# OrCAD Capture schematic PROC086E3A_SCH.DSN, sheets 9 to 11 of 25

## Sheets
9 10. CODEC-A STEREO_LINE_OUT: size C; title: CODEC-A STEREO LINE OUT
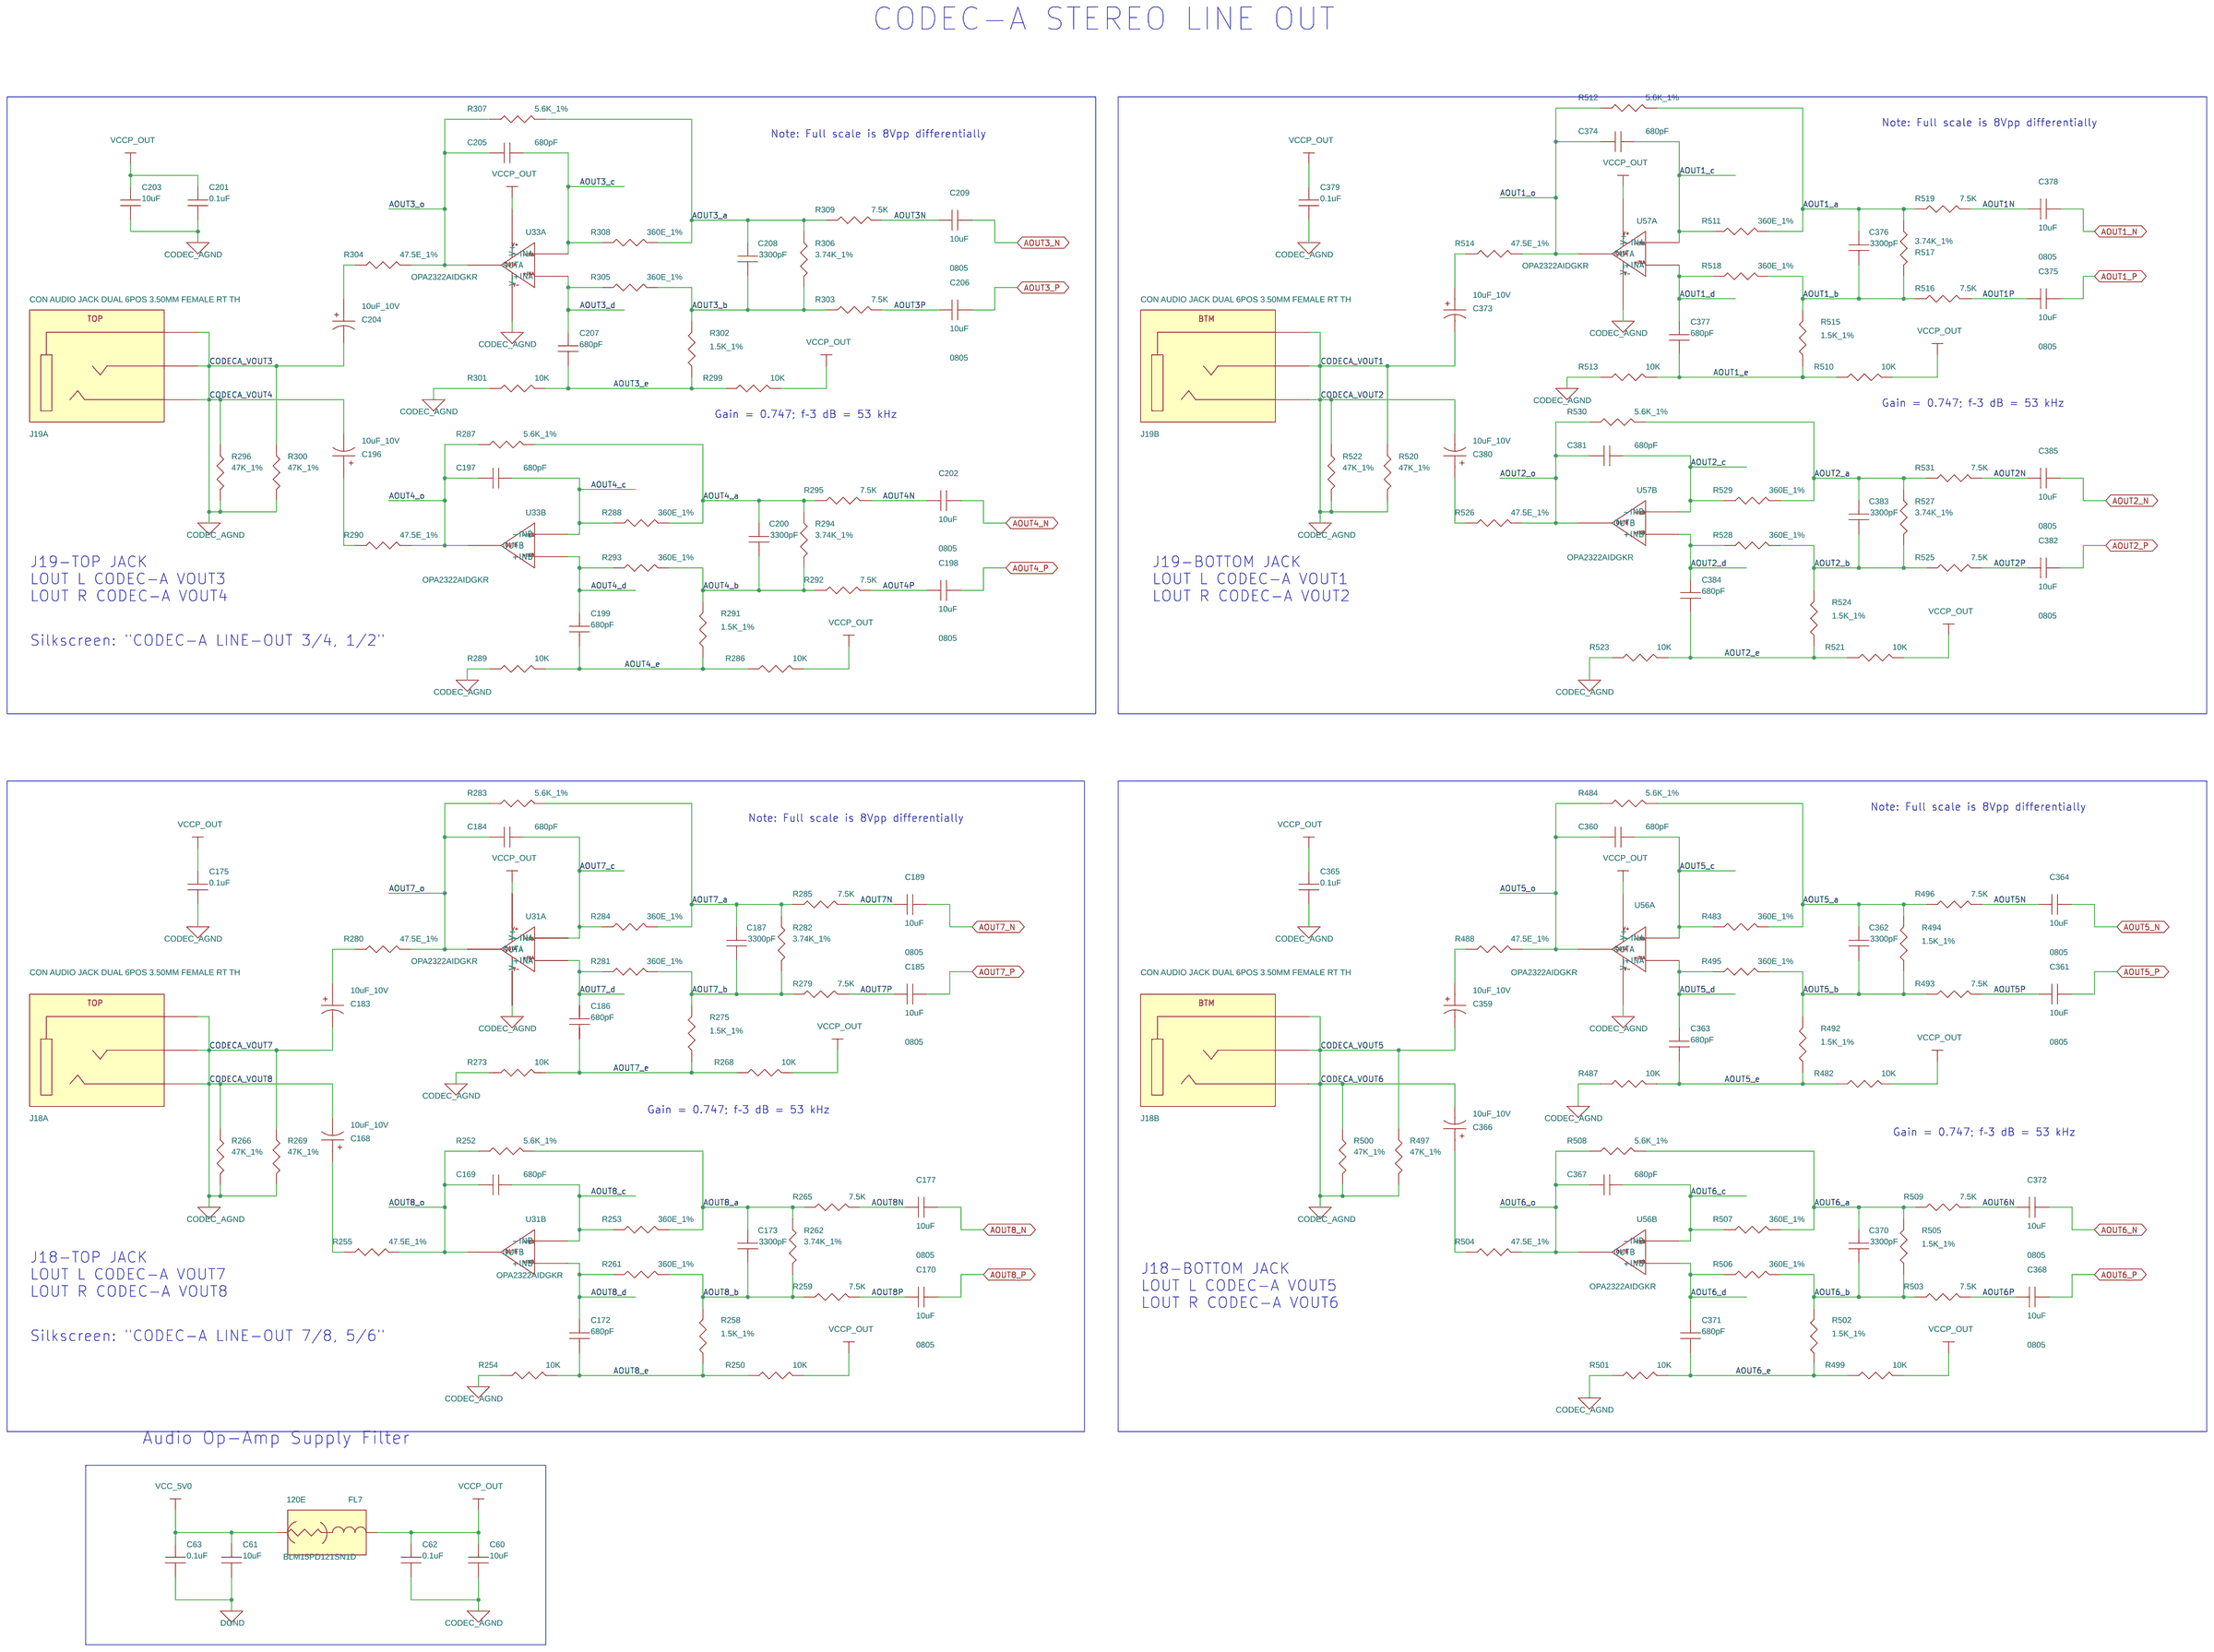
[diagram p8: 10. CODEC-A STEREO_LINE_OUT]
10 12. CODEC-B STEREO_LINE_IN: size C; title: CODEC-B STEREO LINE IN
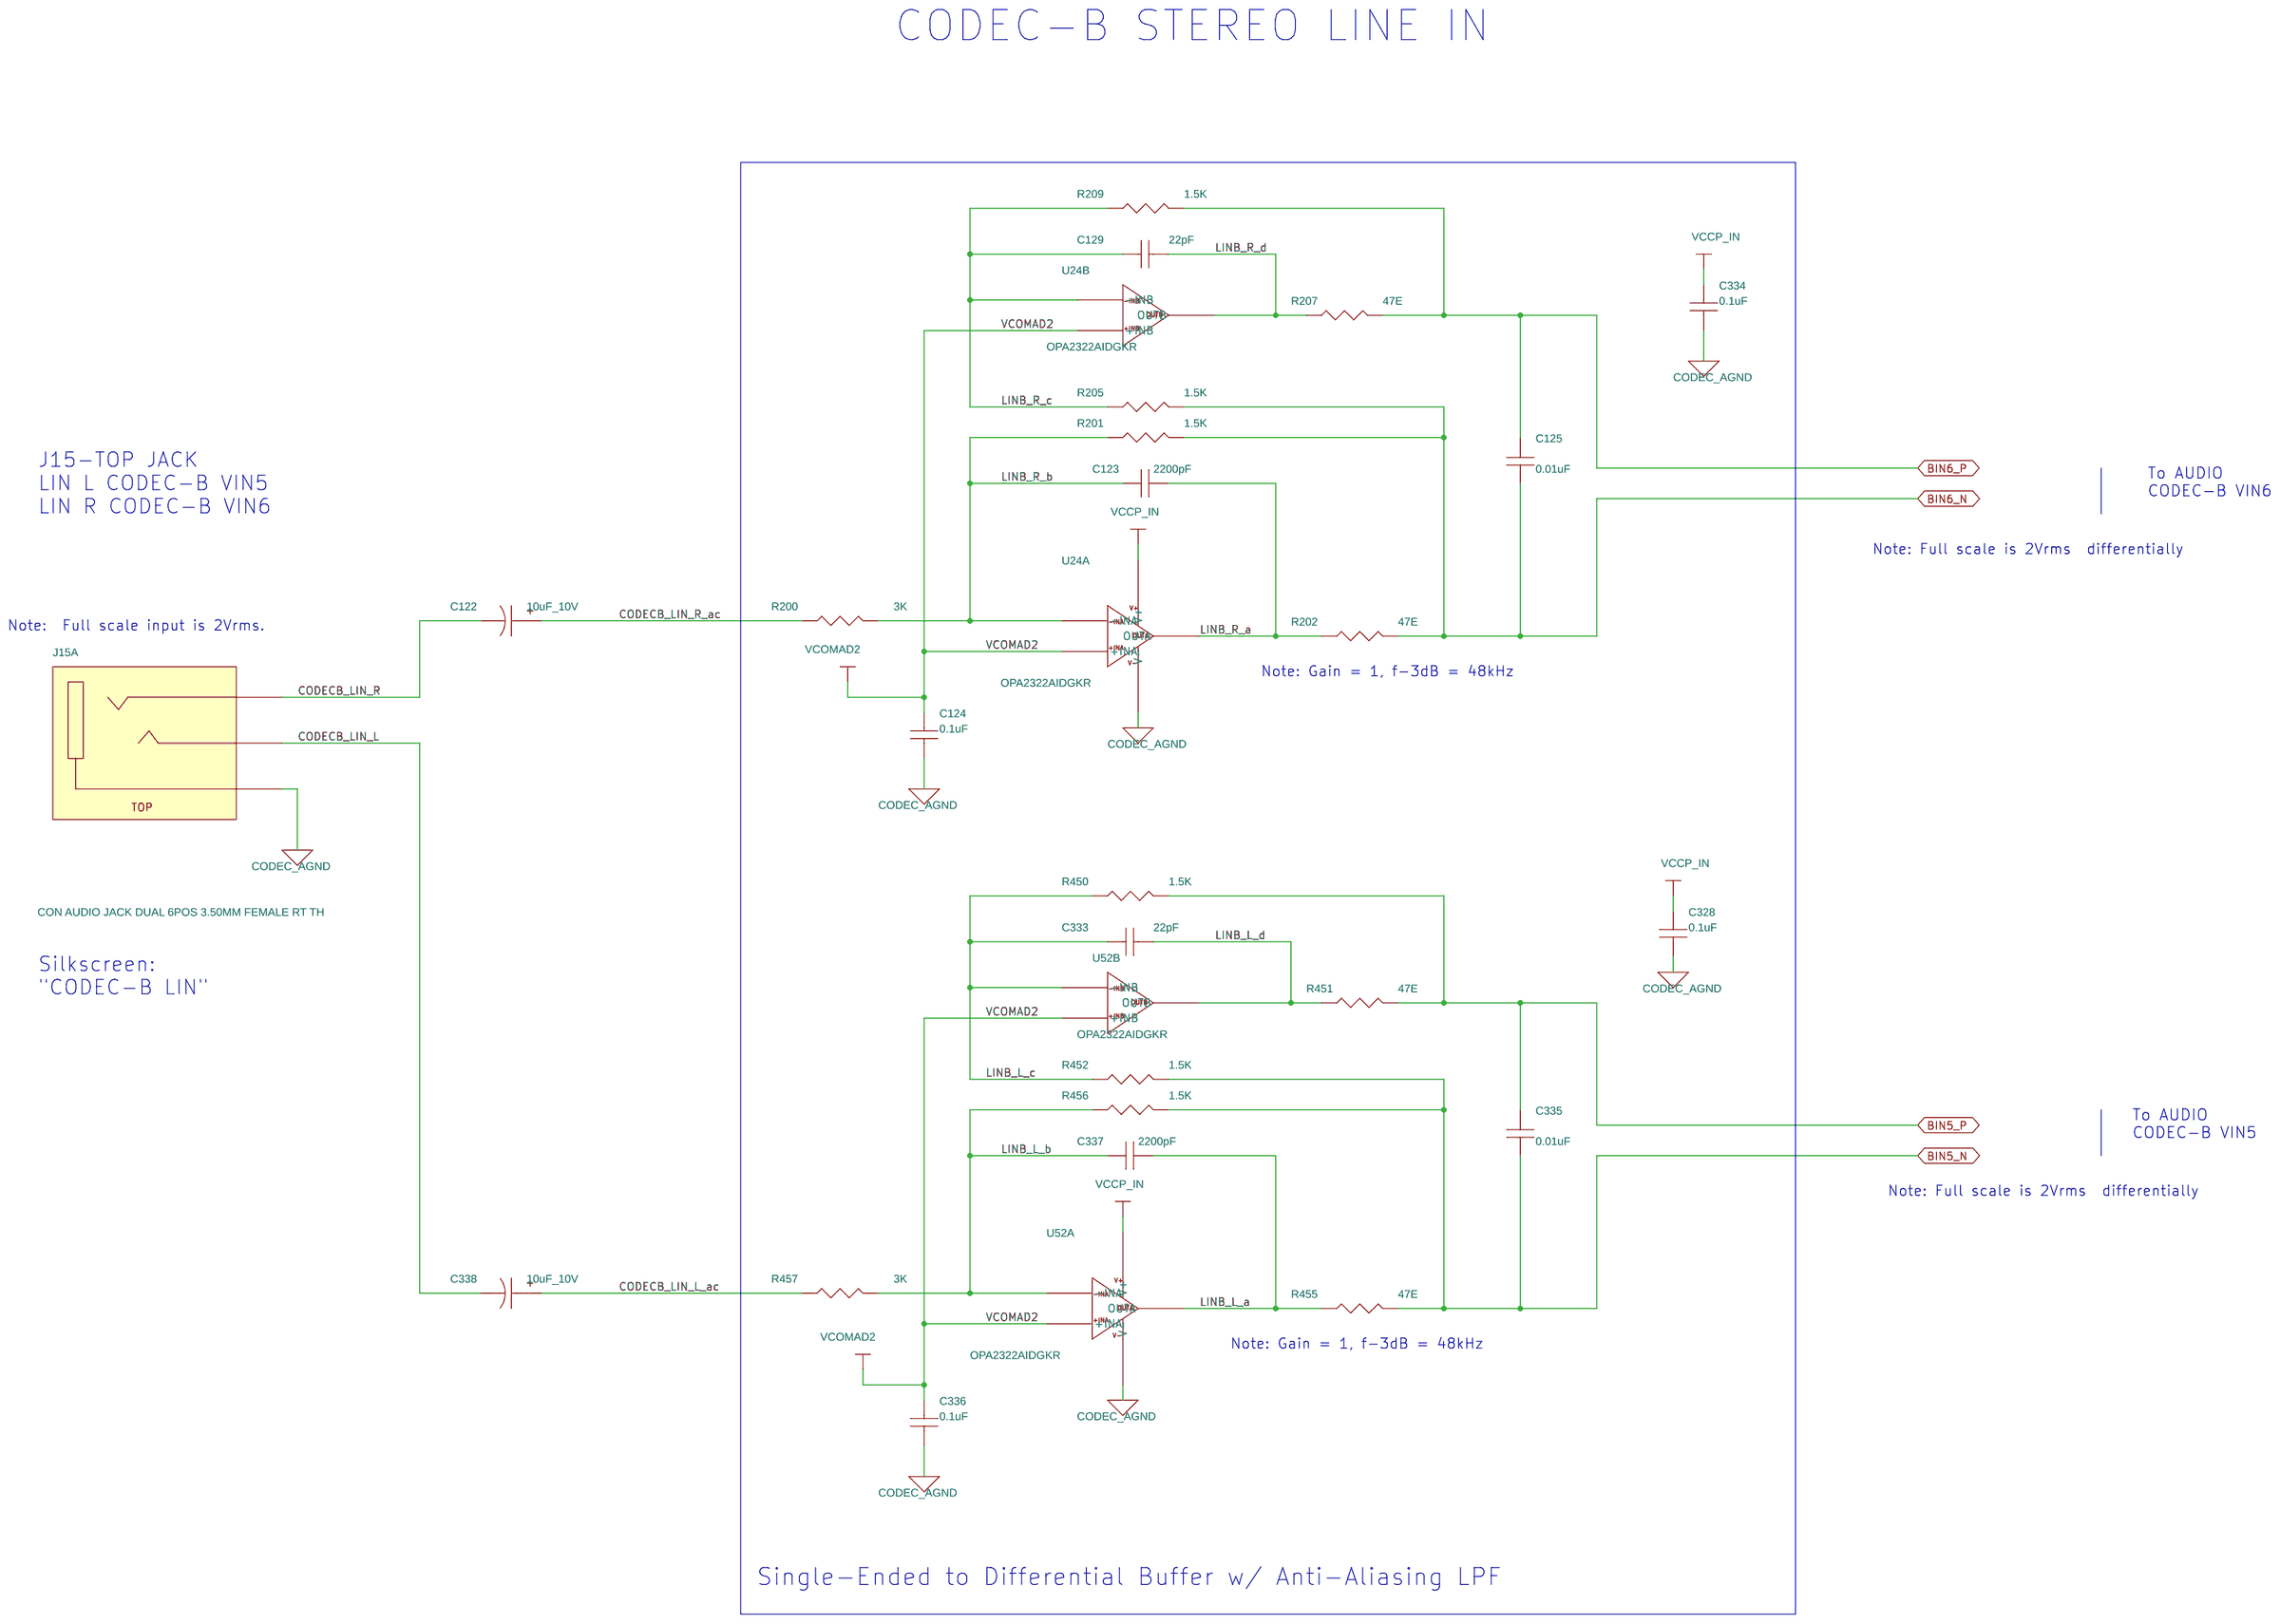
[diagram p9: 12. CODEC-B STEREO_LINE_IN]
11 13. CODEC-B STEREO_MIC 1: size C; title: CODEC-B STEREO MIC 1
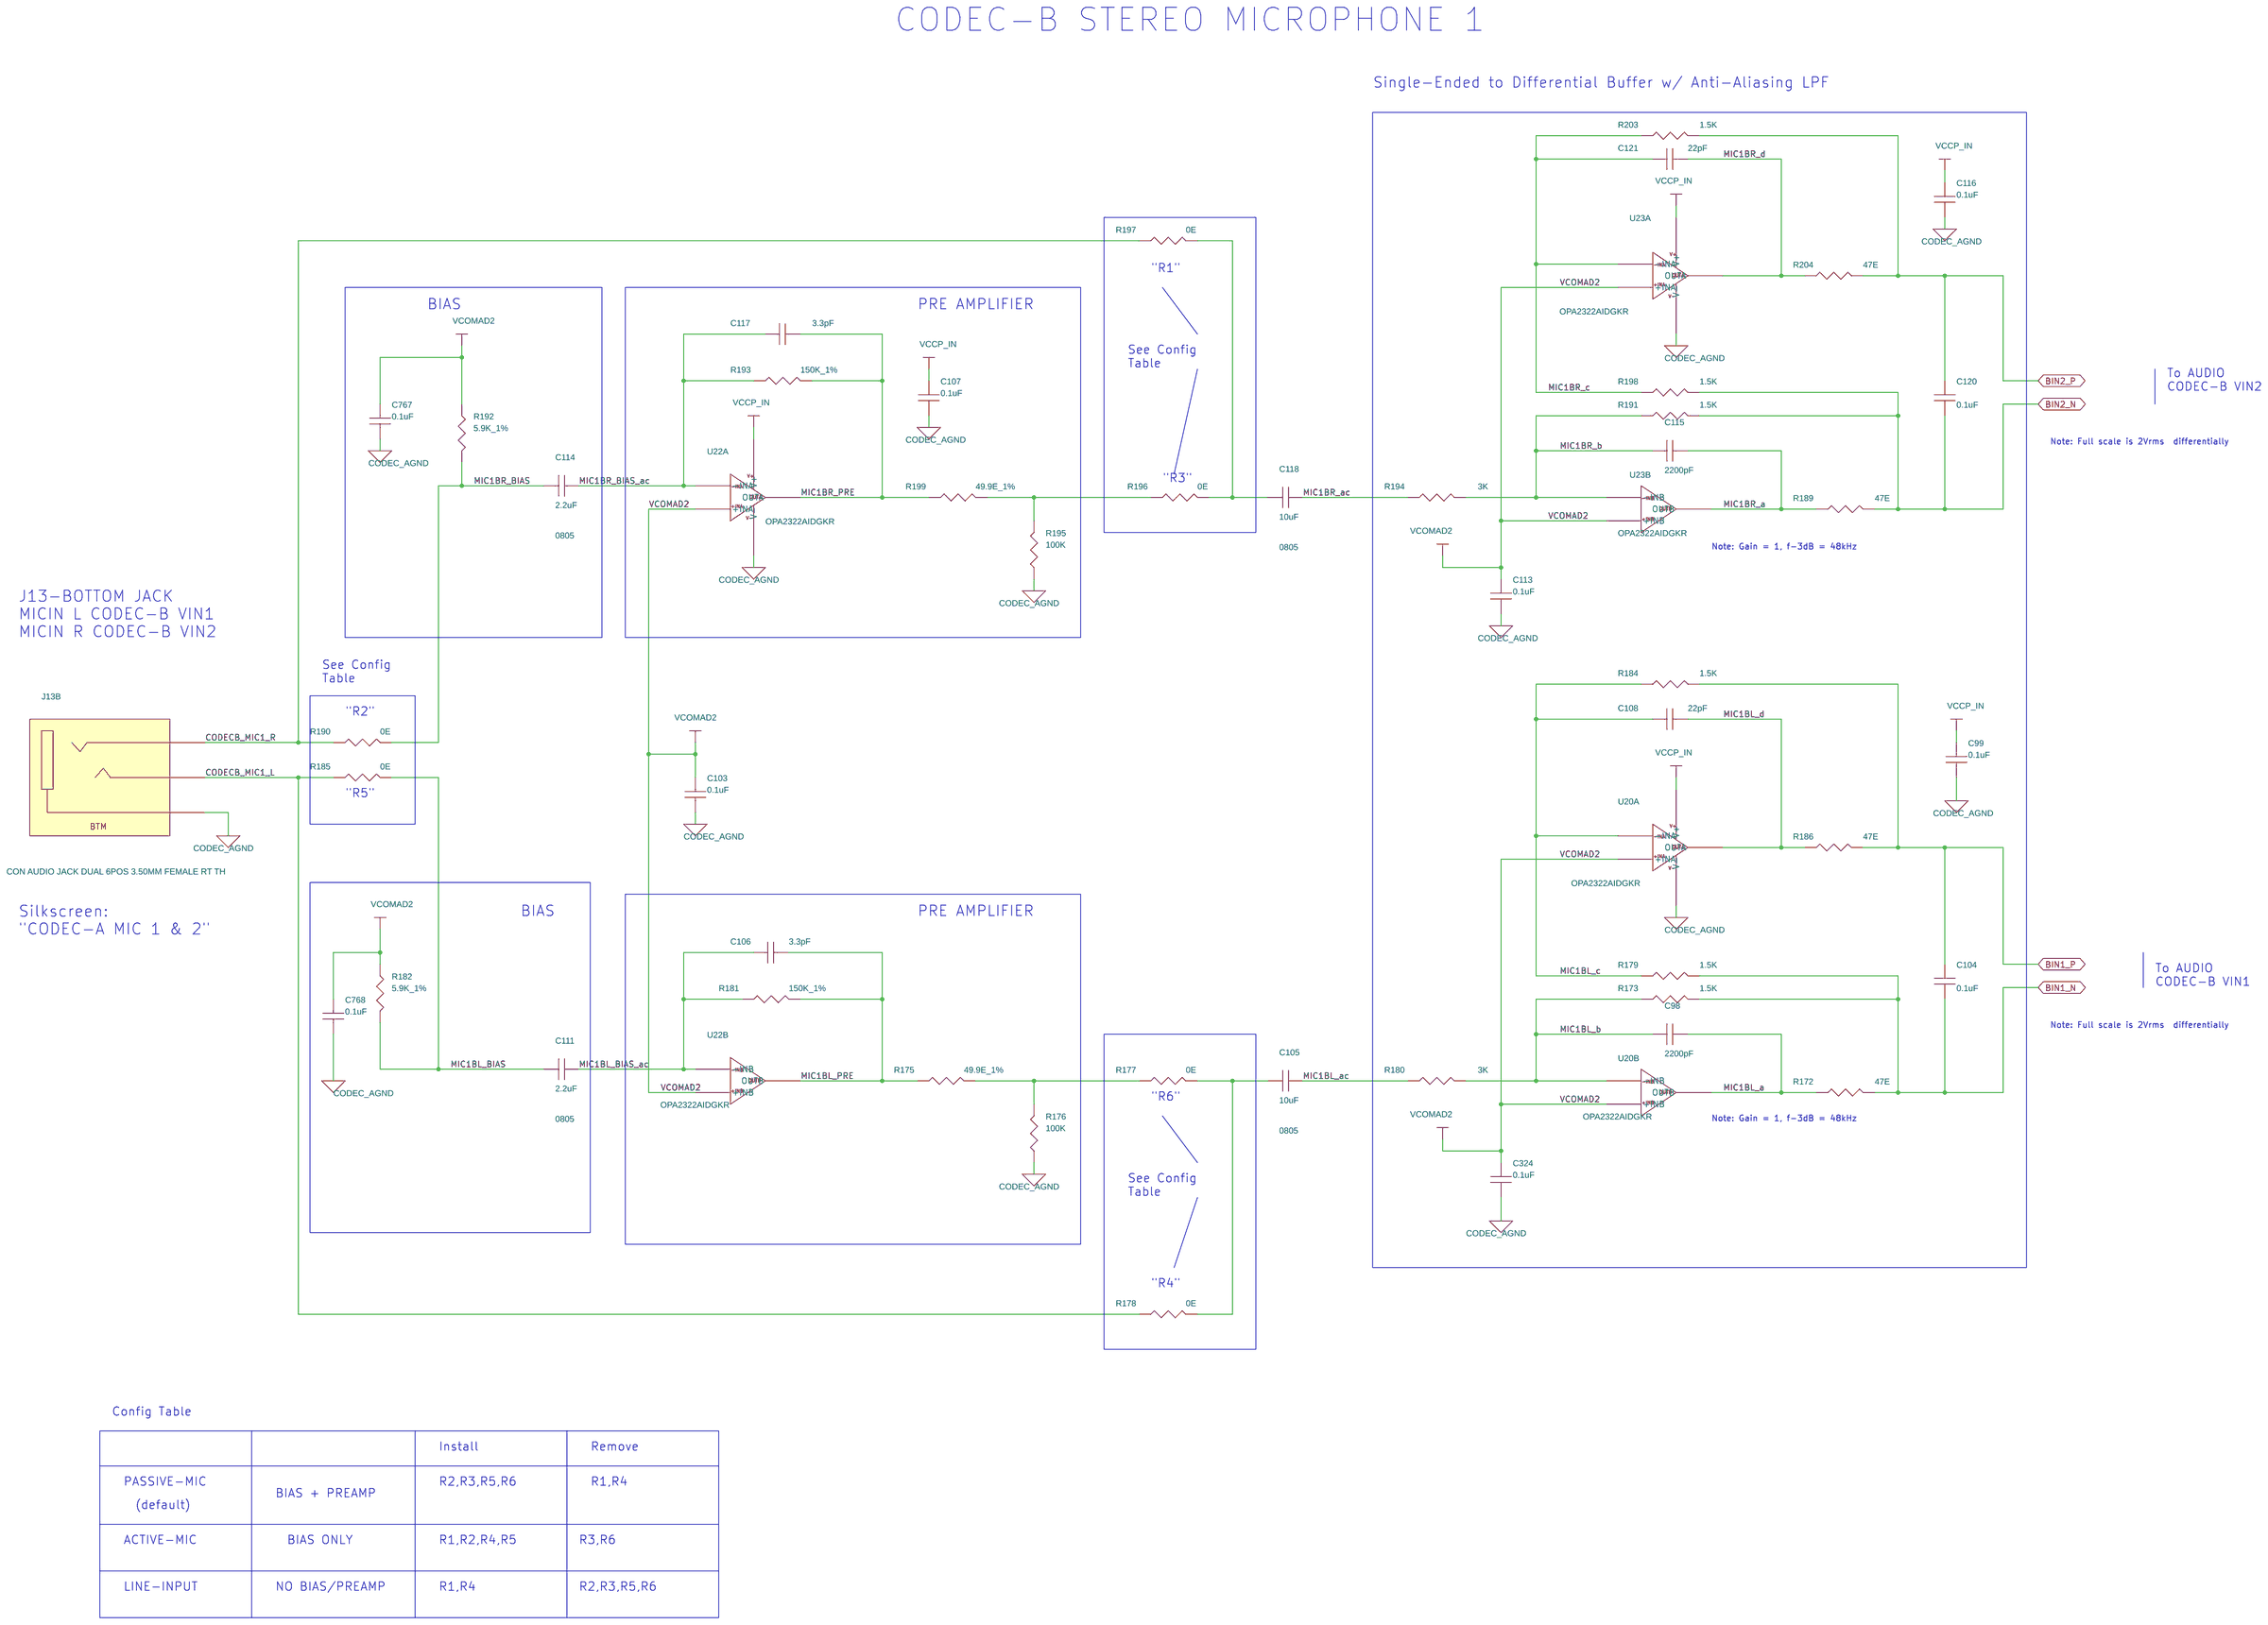
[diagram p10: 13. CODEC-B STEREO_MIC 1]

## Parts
sheet 07. CODEC-A STEREO_LINE_IN
J15  CON_AUDIOJACK6_STX-4235  [CON_AV6_STX-4235-3-3_S_R_T_26]  (sections A,B)
sheet 10. CODEC-A STEREO_LINE_OUT
C60  10uF  [CAP0603_1]
C61  10uF  [CAP0603_1]
C62  0.1uF  [CAP0402_0-75]
C63  0.1uF  [CAP0402_0-75]
C168  10uF_10V  [CAPCT0805H_1]
C169  680pF  [CAP0402_0-75]
C170  10uF  [CAP0805_1-5]
C172  680pF  [CAP0402_0-75]
C173  3300pF  [CAP0402_0-75]
C175  0.1uF  [CAP0402_0-75]
C177  10uF  [CAP0805_1-5]
C183  10uF_10V  [CAPCT0805H_1]
C184  680pF  [CAP0402_0-75]
C185  10uF  [CAP0805_1-5]
C186  680pF  [CAP0402_0-75]
C187  3300pF  [CAP0402_0-75]
C189  10uF  [CAP0805_1-5]
C196  10uF_10V  [CAPCT0805H_1]
C197  680pF  [CAP0402_0-75]
C198  10uF  [CAP0805_1-5]
C199  680pF  [CAP0402_0-75]
C200  3300pF  [CAP0402_0-75]
C201  0.1uF  [CAP0402_0-75]
C202  10uF  [CAP0805_1-5]
C203  10uF  [CAP0603_1]
C204  10uF_10V  [CAPCT0805H_1]
C205  680pF  [CAP0402_0-75]
C206  10uF  [CAP0805_1-5]
C207  680pF  [CAP0402_0-75]
C208  3300pF  [CAP0402_0-75]
C209  10uF  [CAP0805_1-5]
C359  10uF_10V  [CAPCT0805H_1]
C360  680pF  [CAP0402_0-75]
C361  10uF  [CAP0805_1-5]
C362  3300pF  [CAP0402_0-75]
C363  680pF  [CAP0402_0-75]
C364  10uF  [CAP0805_1-5]
C365  0.1uF  [CAP0402_0-75]
C366  10uF_10V  [CAPCT0805H_1]
C367  680pF  [CAP0402_0-75]
C368  10uF  [CAP0805_1-5]
C370  3300pF  [CAP0402_0-75]
C371  680pF  [CAP0402_0-75]
C372  10uF  [CAP0805_1-5]
C373  10uF_10V  [CAPCT0805H_1]
C374  680pF  [CAP0402_0-75]
C375  10uF  [CAP0805_1-5]
C376  3300pF  [CAP0402_0-75]
C377  680pF  [CAP0402_0-75]
C378  10uF  [CAP0805_1-5]
C379  0.1uF  [CAP0402_0-75]
C380  10uF_10V  [CAPCT0805H_1]
C381  680pF  [CAP0402_0-75]
C382  10uF  [CAP0805_1-5]
C383  3300pF  [CAP0402_0-75]
C384  680pF  [CAP0402_0-75]
C385  10uF  [CAP0805_1-5]
FL7  120E  [EMIFIL_BLM15A_0402_0-6]
J18  CON_AUDIOJACK6_STX-4235  [CON_AV6_STX-4235-3-3_S_R_T_26]  (sections A,B)
J19  CON_AUDIOJACK6_STX-4235  [CON_AV6_STX-4235-3-3_S_R_T_26]  (sections A,B)
R250  10K  [RES0402_0-5]
R252  5.6K_1%  [RES0402_0-5]
R253  360E_1%  [RES0402_0-5]
R254  10K  [RES0402_0-5]
R255  47.5E_1%  [RES0402_0-5]
R258  1.5K_1%  [RES0402_0-5]
R259  7.5K  [RES0402_0-5]
R261  360E_1%  [RES0402_0-5]
R262  3.74K_1%  [RES0402_0-5]
R265  7.5K  [RES0402_0-5]
R266  47K_1%  [RES0402_0-5]
R268  10K  [RES0402_0-5]
R269  47K_1%  [RES0402_0-5]
R273  10K  [RES0402_0-5]
R275  1.5K_1%  [RES0402_0-5]
R279  7.5K  [RES0402_0-5]
R280  47.5E_1%  [RES0402_0-5]
R281  360E_1%  [RES0402_0-5]
R282  3.74K_1%  [RES0402_0-5]
R283  5.6K_1%  [RES0402_0-5]
R284  360E_1%  [RES0402_0-5]
R285  7.5K  [RES0402_0-5]
R286  10K  [RES0402_0-5]
R287  5.6K_1%  [RES0402_0-5]
R288  360E_1%  [RES0402_0-5]
R289  10K  [RES0402_0-5]
R290  47.5E_1%  [RES0402_0-5]
R291  1.5K_1%  [RES0402_0-5]
R292  7.5K  [RES0402_0-5]
R293  360E_1%  [RES0402_0-5]
R294  3.74K_1%  [RES0402_0-5]
R295  7.5K  [RES0402_0-5]
R296  47K_1%  [RES0402_0-5]
R299  10K  [RES0402_0-5]
R300  47K_1%  [RES0402_0-5]
R301  10K  [RES0402_0-5]
R302  1.5K_1%  [RES0402_0-5]
R303  7.5K  [RES0402_0-5]
R304  47.5E_1%  [RES0402_0-5]
R305  360E_1%  [RES0402_0-5]
R306  3.74K_1%  [RES0402_0-5]
R307  5.6K_1%  [RES0402_0-5]
R308  360E_1%  [RES0402_0-5]
R309  7.5K  [RES0402_0-5]
R482  10K  [RES0402_0-5]
R483  360E_1%  [RES0402_0-5]
R484  5.6K_1%  [RES0402_0-5]
R487  10K  [RES0402_0-5]
R488  47.5E_1%  [RES0402_0-5]
R492  1.5K_1%  [RES0402_0-5]
R493  7.5K  [RES0402_0-5]
R494  1.5K_1%  [RES0402_0-5]
R495  360E_1%  [RES0402_0-5]
R496  7.5K  [RES0402_0-5]
R497  47K_1%  [RES0402_0-5]
R499  10K  [RES0402_0-5]
R500  47K_1%  [RES0402_0-5]
R501  10K  [RES0402_0-5]
R502  1.5K_1%  [RES0402_0-5]
R503  7.5K  [RES0402_0-5]
R504  47.5E_1%  [RES0402_0-5]
R505  1.5K_1%  [RES0402_0-5]
R506  360E_1%  [RES0402_0-5]
R507  360E_1%  [RES0402_0-5]
R508  5.6K_1%  [RES0402_0-5]
R509  7.5K  [RES0402_0-5]
R510  10K  [RES0402_0-5]
R511  360E_1%  [RES0402_0-5]
R512  5.6K_1%  [RES0402_0-5]
R513  10K  [RES0402_0-5]
R514  47.5E_1%  [RES0402_0-5]
R515  1.5K_1%  [RES0402_0-5]
R516  7.5K  [RES0402_0-5]
R517  3.74K_1%  [RES0402_0-5]
R518  360E_1%  [RES0402_0-5]
R519  7.5K  [RES0402_0-5]
R520  47K_1%  [RES0402_0-5]
R521  10K  [RES0402_0-5]
R522  47K_1%  [RES0402_0-5]
R523  10K  [RES0402_0-5]
R524  1.5K_1%  [RES0402_0-5]
R525  7.5K  [RES0402_0-5]
R526  47.5E_1%  [RES0402_0-5]
R527  3.74K_1%  [RES0402_0-5]
R528  360E_1%  [RES0402_0-5]
R529  360E_1%  [RES0402_0-5]
R530  5.6K_1%  [RES0402_0-5]
R531  7.5K  [RES0402_0-5]
U31  OPA2322AIDGKR  [VSSOP8_25-59_120X120_1-1]  (sections A,B)
U33  OPA2322AIDGKR  [VSSOP8_25-59_120X120_1-1]  (sections A,B)
U56  OPA2322AIDGKR  [VSSOP8_25-59_120X120_1-1]  (sections A,B)
U57  OPA2322AIDGKR  [VSSOP8_25-59_120X120_1-1]  (sections A,B)
sheet 12. CODEC-B STEREO_LINE_IN
C122  10uF_10V  [CAPCT0805H_1]
C123  2200pF  [CAP0402_0-75]
C124  0.1uF  [CAP0402_0-75]
C125  0.01uF  [CAP0402_0-75]
C129  22pF  [CAP0402_0-75]
C328  0.1uF  [CAP0402_0-75]
C333  22pF  [CAP0402_0-75]
C334  0.1uF  [CAP0402_0-75]
C335  0.01uF  [CAP0402_0-75]
C336  0.1uF  [CAP0402_0-75]
C337  2200pF  [CAP0402_0-75]
C338  10uF_10V  [CAPCT0805H_1]
R200  3K  [RES0402_0-5]
R201  1.5K  [RES0402_0-5]
R202  47E  [RES0402_0-5]
R205  1.5K  [RES0402_0-5]
R207  47E  [RES0402_0-5]
R209  1.5K  [RES0402_0-5]
R450  1.5K  [RES0402_0-5]
R451  47E  [RES0402_0-5]
R452  1.5K  [RES0402_0-5]
R455  47E  [RES0402_0-5]
R456  1.5K  [RES0402_0-5]
R457  3K  [RES0402_0-5]
U24  OPA2322AIDGKR  [VSSOP8_25-59_120X120_1-1]  (sections A,B)
U52  OPA2322AIDGKR  [VSSOP8_25-59_120X120_1-1]  (sections A,B)
sheet 13. CODEC-B STEREO_MIC 1
C98  2200pF  [CAP0402_0-75]
C99  0.1uF  [CAP0402_0-75]
C103  0.1uF  [CAP0402_0-75]
C104  0.1uF  [CAP0402_0-75]
C105  10uF  [CAP0805_1-5]
C106  3.3pF  [CAP0402_0-75]
C107  0.1uF  [CAP0402_0-75]
C108  22pF  [CAP0402_0-75]
C111  2.2uF  [CAP0805_1-5]
C113  0.1uF  [CAP0402_0-75]
C114  2.2uF  [CAP0805_1-5]
C115  2200pF  [CAP0402_0-75]
C116  0.1uF  [CAP0402_0-75]
C117  3.3pF  [CAP0402_0-75]
C118  10uF  [CAP0805_1-5]
C120  0.1uF  [CAP0402_0-75]
C121  22pF  [CAP0402_0-75]
C324  0.1uF  [CAP0402_0-75]
C767  0.1uF  [CAP0402_0-75]
C768  0.1uF  [CAP0402_0-75]
J13  CON_AUDIOJACK6_STX-4235  [CON_AV6_STX-4235-3-3_S_R_T_26]  (sections A,B)
R172  47E  [RES0402_0-5]
R173  1.5K  [RES0402_0-5]
R175  49.9E_1%  [RES0402_0-5]
R176  100K  [RES0402_0-5]
R177  0E  [RES0402_0-5]
R178  0E  [RES0402_0-5]
R179  1.5K  [RES0402_0-5]
R180  3K  [RES0402_0-5]
R181  150K_1%  [RES0402_0-5]
R182  5.9K_1%  [RES0402_0-5]
R184  1.5K  [RES0402_0-5]
R185  0E  [RES0402_0-5]
R186  47E  [RES0402_0-5]
R189  47E  [RES0402_0-5]
R190  0E  [RES0402_0-5]
R191  1.5K  [RES0402_0-5]
R192  5.9K_1%  [RES0402_0-5]
R193  150K_1%  [RES0402_0-5]
R194  3K  [RES0402_0-5]
R195  100K  [RES0402_0-5]
R196  0E  [RES0402_0-5]
R197  0E  [RES0402_0-5]
R198  1.5K  [RES0402_0-5]
R199  49.9E_1%  [RES0402_0-5]
R203  1.5K  [RES0402_0-5]
R204  47E  [RES0402_0-5]
U20  OPA2322AIDGKR  [VSSOP8_25-59_120X120_1-1]  (sections A,B)
U22  OPA2322AIDGKR  [VSSOP8_25-59_120X120_1-1]  (sections A,B)
U23  OPA2322AIDGKR  [VSSOP8_25-59_120X120_1-1]  (sections A,B)

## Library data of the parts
J13 J15 J18 J19 = CON_AUDIOJACK6_STX-4235-3_3: CON AUDIO JACK DUAL 6POS 3.50MM FEMALE RT TH; Chkd/date: MANIRAJA/090818; Crtd /date: ALVY/080818; Custom_Duty: 24%; Customs_HS_Code: 85369090; Distributor_name: MOUSER; Distributor_part_number: 806-STX-4235-3/3-N; Footprint Path: Y:\MIS_DATABASE\Library\ALTIUM_TOOL\PCB_FOOTPRINTS\Altium_Footprint_Lib.PcbLib; Height: 26.00MM; Library Path: Y:\MIS_DATABASE\Library\ALTIUM_TOOL\SCHEMATICS_PARTS\MS_CONNECTOR_Library.schlib; Library Ref: CON_AUDIOJACK6_STX-4235-3/3; Mfr_name: KYCON; Mfr_part_number: STX-4235-3/3-N; Mistral Part No: 150018080005-R; Package: THRU-HOLE; Part_type: CONNECTOR\JACK; Project: TI_J7ES_EVM_FUSION2_SER_CAP; RoHS: RoHS; Temperature: -25°C+85°C; Tolerance: NA; Voltage: NA; Wattage: NA; Weight: NA; Datasheet: Y:\MIS_DATABASE\DATASHEETS\CONNECTORS\STX-4235-3-3-N.PDF
C60 C61 C203 = CAP: CAP CERAMIC 10uF 16V 20% X6S 0603; Chkd/date: VASANTHA/170117; Crtd /date: VASANTHA/170117; Custom_Duty: 15%; Customs_HS_Code: 85322990; Distributor_name: DIGIKEY; Distributor_part_number: 490-7198-1-ND; Footprint Path: Y:\MIS_DATABASE\Library\ALTIUM_TOOL\PCB_FOOTPRINTS\Altium_Footprint_Lib.PcbLib; Height: 0.90MM; Library Path: Y:\MIS_DATABASE\Library\ALTIUM_TOOL\SCHEMATICS_PARTS\MS_DISCRETE_Library.schlib; Mfr_name: MURATA; Mfr_part_number: GRM188C81C106MA73D; Mistral Part No: 120017010004-R; Package: 0603; Part_type: CAPACITORS\CERAMIC; Project: TRMM_SMART-M_PS; RoHS: RoHS; Temperature: -55°C+105°C; Tolerance: 20%; Voltage: 16V; Wattage: NA; Weight: 6.3mg; Datasheet: Y:\MIS_DATABASE\DATASHEETS\CAPACITORS\MURATA-GXX-SER_NOV17.PDF
C62 C63 C99 C103 C104 C107 C113 C116 C120 C124 C175 C201 C324 C328 C334 C336 C365 C379 C767 C768 = CAP: CAP CERAMIC 0.1uF 50V 10% X7R 0402; Chkd/date: VASANTHA/281216; Crtd /date: CHAITHANYA/051011; Custom_Duty: 15%; Customs_HS_Code: 85322990; Distributor_name: DIGIKEY; Distributor_part_number: 445-173610-1-ND; Footprint Path: Y:\MIS_DATABASE\Library\ALTIUM_TOOL\PCB_FOOTPRINTS\Altium_Footprint_Lib.PcbLib; Height: 0.60MM; Library Path: Y:\MIS_DATABASE\Library\ALTIUM_TOOL\SCHEMATICS_PARTS\MS_DISCRETE_Library.schlib; Mfr_name: TDK CORPORATION; Mfr_part_number: C1005X7R1H104K050BE; Mistral Part No: 120011100014-R; Package: 0402; Part_type: CAPACITORS\CERAMIC; Project: VP-4000-BASE-BOARD; RoHS: RoHS; Temperature: -55°C+125°C; Tolerance: 10%; Voltage: 50V; Wattage: NA; Weight: 0.65mg; Datasheet: Y:\MIS_DATABASE\DATASHEETS\CAPACITORS\TDK_C-SER_FEB19.PDF
C122 C168 C183 C196 C204 C338 C359 C366 C373 C380 = CAP_POL: CAP TANTALUM 10uF 10V 20% ESR 5E H0805; Chkd/date: MANIRAJA/091018; Crtd /date: ALVY/091018; Custom_Duty: 15%; Customs_HS_Code: 85322990; Distributor_name: DIGIKEY; Distributor_part_number: 478-11046-1-ND; Footprint Path: Y:\MIS_DATABASE\Library\ALTIUM_TOOL\PCB_FOOTPRINTS\Altium_Footprint_Lib.PcbLib; Height: 1.00MM; Library Path: Y:\MIS_DATABASE\Library\ALTIUM_TOOL\SCHEMATICS_PARTS\MS_DISCRETE_Library.schlib; Mfr_name: AVX CORPORATION; Mfr_part_number: TACH106M010XTA; Mistral Part No: 120018100018-R; Package: H0805; Part_type: CAPACITORS\TANTALUM; Project: TI_J7ES_EVM_CP; RoHS: RoHS; Temperature: -55°C+125°C; Tolerance: 20%; Voltage: 10V; Wattage: NA; Weight: 5.5mg; Datasheet: Y:\MIS_DATABASE\DATASHEETS\CAPACITORS\AVX-TAC-APR18.PDF
C169 C172 C184 C186 C197 C199 C205 C207 C360 C363 C367 C371 C374 C377 C381 C384 = CAP: CAP CERAMIC 680pF 50V 5% X7R 0402; Chkd/date: BAVISH/260911; Crtd /date: CHAITHANYA/260911; Custom_Duty: 15%; Customs_HS_Code: 85322990; Distributor_name: DIGIKEY; Distributor_part_number: 478-5270-1-ND; Footprint Path: Y:\MIS_DATABASE\Library\ALTIUM_TOOL\PCB_FOOTPRINTS\Altium_Footprint_Lib.PcbLib; Height: 0.56MM; Library Path: Y:\MIS_DATABASE\Library\ALTIUM_TOOL\SCHEMATICS_PARTS\MS_DISCRETE_Library.schlib; Mfr_name: AVX CORPORATION; Mfr_part_number: 04025C681JAT2A; Mistral Part No: 120011090031-R; Package: 0402; Part_type: CAPACITORS\CERAMIC; Project: GEMYC; RoHS: RoHS; Temperature: -55°C+125°C; Tolerance: 5%; Voltage: 50V; Wattage: NA; Weight: 0.65mg; Datasheet: Y:\MIS_DATABASE\DATASHEETS\CAPACITORS\AVX_MLC.PDF
C105 C118 C170 C177 C185 C189 C198 C202 C206 C209 C361 C364 C368 C372 C375 C378 C382 C385 = CAP: CAP CERAMIC 10uF 16V 10% X5R 0805; Chkd/date: SHREESHAIL/220506; Crtd /date: MAZHAR/150506; Custom_Duty: 15%; Customs_HS_Code: 85322990; Distributor_name: DIGIKEY; Distributor_part_number: 490-3886-1-ND; Footprint Path: Y:\MIS_DATABASE\Library\ALTIUM_TOOL\PCB_FOOTPRINTS\Altium_Footprint_Lib.PcbLib; Height: 1.35MM; Library Path: Y:\MIS_DATABASE\Library\ALTIUM_TOOL\SCHEMATICS_PARTS\MS_DISCRETE_Library.schlib; Mfr_name: MURATA; Mfr_part_number: GRM21BR61C106KE15L; Mistral Part No: 120009030205-R; Package: 0805; Part_type: CAPACITORS\CERAMIC; Project: VOCERA; RoHS: RoHS; Temperature: -55°C+85°C; Tolerance: 10%; Voltage: 16V; Wattage: NA; Weight: 9.5mg; Datasheet: Y:\MIS_DATABASE\DATASHEETS\CAPACITORS\MURATA-GXX-SER_NOV17.PDF
C173 C187 C200 C208 C362 C370 C376 C383 = CAP: CAP CERAMIC 3300pF 50V 10% X7R 0402; Chkd/date: MAZHAR/241208; Crtd /date: USMAN/131108; Custom_Duty: 15%; Customs_HS_Code: 85322990; Distributor_name: DIGIKEY; Distributor_part_number: 478-1107-1-ND; Footprint Path: Y:\MIS_DATABASE\Library\ALTIUM_TOOL\PCB_FOOTPRINTS\Altium_Footprint_Lib.PcbLib; Height: 0.56MM; Library Path: Y:\MIS_DATABASE\Library\ALTIUM_TOOL\SCHEMATICS_PARTS\MS_DISCRETE_Library.schlib; Mfr_name: AVX CORPORATION; Mfr_part_number: 04025C332KAT2A; Mistral Part No: 120009030367-R; Package: 0402; Part_type: CAPACITORS\CERAMIC; Project: P2ER6DB; RoHS: RoHS; Temperature: -55°C+125°C; Tolerance: 10%; Voltage: 50V; Wattage: NA; Weight: 0.65mg; Datasheet: Y:\MIS_DATABASE\DATASHEETS\CAPACITORS\AVX_MLC.PDF
FL7 = EMIFILTER_IND: IND FERRITE BEAD CHIP 120E 1.3A 0402; Chkd/date: VASANTHA/010117; Crtd /date: CHAITHANYA/150312; Custom_Duty: 24%; Customs_HS_Code: 85437099; Distributor_name: DIGIKEY; Distributor_part_number: 490-5203-1-ND; Footprint Path: Y:\MIS_DATABASE\Library\ALTIUM_TOOL\PCB_FOOTPRINTS\Altium_Footprint_Lib.PcbLib; Height: 0.55MM; Library Path: Y:\MIS_DATABASE\Library\ALTIUM_TOOL\SCHEMATICS_PARTS\MS_FILTER_Library.schlib; Mfr_name: MURATA; Mfr_part_number: BLM15PD121SN1D; Mistral Part No: 130012030043-R; Package: 0402; Part_type: FILTER; Project: GEN_3-8; RoHS: RoHS; Temperature: -55°C+125°C; Tolerance: 25%; Voltage: NA; Wattage: NA; Weight: 0.65mg; Datasheet: Y:\MIS_DATABASE\DATASHEETS\DISCRETES\INDUCTORS\BLM15X-SER.PDF
R250 R254 R268 R273 R286 R289 R299 R301 R482 R487 R499 R501 R510 R513 R521 R523 = RESISTOR: RES 10K 1/16W 5% 0402; Chkd/date: VASANTHA/061216; Crtd /date: MAZHAR/230805; Custom_Duty: 15%; Customs_HS_Code: 85332119; Distributor_name: DIGIKEY; Distributor_part_number: 311-10KJRCT-ND; Footprint Path: Y:\MIS_DATABASE\Library\ALTIUM_TOOL\PCB_FOOTPRINTS\Altium_Footprint_Lib.PcbLib; Height: 0.40MM; Library Path: Y:\MIS_DATABASE\Library\ALTIUM_TOOL\SCHEMATICS_PARTS\MS_DISCRETE_Library.schlib; Mfr_name: YAGEO AMERICA; Mfr_part_number: RC0402JR-0710KL; Mistral Part No: 110011060021-R; Package: 0402; Part_type: RESISTORS\FIXED; Project: HSE; RoHS: RoHS; Temperature: -55°C+155°C; Tolerance: 5%; Voltage: NA; Wattage: 1/16W; Weight: 0.65mg; Datasheet: Y:\MIS_DATABASE\DATASHEETS\RESISTORS\RCXXXXL-SER_MAR18.PDF
R252 R283 R287 R307 R484 R508 R512 R530 = RESISTOR: RES 5.6K 1/16W 1% 0402; Chkd/date: MANIRAJA/050517; Crtd /date: MANIRAJA/050517; Custom_Duty: 15%; Customs_HS_Code: 85332119; Distributor_name: DIGIKEY; Distributor_part_number: 311-5.6KLRCT-ND; Footprint Path: Y:\MIS_DATABASE\Library\ALTIUM_TOOL\PCB_FOOTPRINTS\Altium_Footprint_Lib.PcbLib; Height: 0.40MM; Library Path: Y:\MIS_DATABASE\Library\ALTIUM_TOOL\SCHEMATICS_PARTS\MS_DISCRETE_Library.schlib; Mfr_name: YAGEO AMERICA; Mfr_part_number: RC0402FR-075K6L; Mistral Part No: 110011100024-R; Package: 0402; Part_type: RESISTORS\FIXED; Project: GOLDEN-I LITE; RoHS: RoHS; Temperature: -55°C+155°C; Tolerance: 1%; Voltage: NA; Wattage: 1/16W; Weight: 0.65mg; Datasheet: Y:\MIS_DATABASE\DATASHEETS\RESISTORS\RCXXXXL-SER_MAR18.PDF
R253 R261 R281 R284 R288 R293 R305 R308 R483 R495 R506 R507 R511 R518 R528 R529 = RESISTOR: RES 360E 1/16W 1% 0402; Chkd/date: Bavish/240111; Crtd /date: MAZHAR/031210; Custom_Duty: 15%; Customs_HS_Code: 85332119; Distributor_name: DIGIKEY; Distributor_part_number: 541-360LCT-ND; Footprint Path: Y:\MIS_DATABASE\Library\ALTIUM_TOOL\PCB_FOOTPRINTS\Altium_Footprint_Lib.PcbLib; Height: 0.40MM; Library Path: Y:\MIS_DATABASE\Library\ALTIUM_TOOL\SCHEMATICS_PARTS\MS_DISCRETE_Library.schlib; Mfr_name: VISHAY; Mfr_part_number: CRCW0402360RFKED; Mistral Part No: 110010120036-R; Package: 0402; Part_type: RESISTORS\FIXED; Project: CPCI3GADC_CARD; RoHS: RoHS; Temperature: -55°C+155°C; Tolerance: 1%; Voltage: NA; Wattage: 1/16W; Weight: 0.65mg; Datasheet: Y:\MIS_DATABASE\DATASHEETS\RESISTORS\CRCW0603.PDF
R255 R280 R290 R304 R488 R504 R514 R526 = RESISTOR: RES 47.5E 1/10W 1% 0402; Chkd/date: MANIRAJA/060619; Crtd /date: MANIRAJA/060619; Custom_Duty: 15%; Customs_HS_Code: 85332119; Distributor_name: DIGIKEY; Distributor_part_number: P47.5LCT-ND; Footprint Path: Y:\MIS_DATABASE\Library\ALTIUM_TOOL\PCB_FOOTPRINTS\Altium_Footprint_Lib.PcbLib; Height: 0.40MM; Library Path: Y:\MIS_DATABASE\Library\ALTIUM_TOOL\SCHEMATICS_PARTS\MS_DISCRETE_Library.schlib; Mfr_name: PANASONIC-ECG; Mfr_part_number: ERJ-2RKF47R5X; Mistral Part No: 110009030855-R; Package: 0402; Part_type: RESISTORS\FIXED; Project: J7ES_SOM_DUAL-LEO_PMIC; RoHS: RoHS; Temperature: -55°C+155°C; Tolerance: 1%; Voltage: NA; Wattage: 1/10W; Weight: 0.8mg; Datasheet: Y:\MIS_DATABASE\DATASHEETS\RESISTORS\PAN-ERJSER_NOV17.PDF
R258 R275 R291 R302 R492 R494 R502 R505 R515 R524 = RESISTOR: RES 1.5K 1/16W 1% 0402; Chkd/date: VASANTHA/201216; Crtd /date: JEBRAN/250815; Custom_Duty: 15%; Customs_HS_Code: 85332119; Distributor_name: DIGIKEY; Distributor_part_number: 311-1.50KLRCT-ND; Footprint Path: Y:\MIS_DATABASE\Library\ALTIUM_TOOL\PCB_FOOTPRINTS\Altium_Footprint_Lib.PcbLib; Height: 0.40MM; Library Path: Y:\MIS_DATABASE\Library\ALTIUM_TOOL\SCHEMATICS_PARTS\MS_DISCRETE_Library.schlib; Mfr_name: YAGEO AMERICA; Mfr_part_number: RC0402FR-071K5L; Mistral Part No: 110015080041-R; Package: 0402; Part_type: RESISTORS\FIXED; Project: OCTBTS3600; RoHS: RoHS; Temperature: -55°C+155°C; Tolerance: 1%; Voltage: NA; Wattage: 1/16W; Weight: 0.65mg; Datasheet: Y:\MIS_DATABASE\DATASHEETS\RESISTORS\RCXXXXL-SER_MAR18.PDF
R259 R265 R279 R285 R292 R295 R303 R309 R493 R496 R503 R509 R516 R519 R525 R531 = RESISTOR: RES 7.5K 1/16W 5% 0402; Chkd/date: MAZHAR/280108; Crtd /date: USMAN/280108; Custom_Duty: 15%; Customs_HS_Code: 85332119; Distributor_name: DIGIKEY; Distributor_part_number: 541-7.5KJCT-ND; Footprint Path: Y:\MIS_DATABASE\Library\ALTIUM_TOOL\PCB_FOOTPRINTS\Altium_Footprint_Lib.PcbLib; Height: 0.40MM; Library Path: Y:\MIS_DATABASE\Library\ALTIUM_TOOL\SCHEMATICS_PARTS\MS_DISCRETE_Library.schlib; Mfr_name: VISHAY; Mfr_part_number: CRCW04027K50JNED; Mistral Part No: 110009031092-R; Package: 0402; Part_type: RESISTORS\FIXED; Project: TELEMETRY ENCODER; RoHS: RoHS; Temperature: -55°C+155°C; Tolerance: 5%; Voltage: NA; Wattage: 1/16W; Weight: 0.65mg; Datasheet: Y:\MIS_DATABASE\DATASHEETS\RESISTORS\CRCW0603.PDF
R262 R282 R294 R306 R517 R527 = RESISTOR: RES 3.74K 1/10W 1% 0402; Chkd/date: MAZHAR/151208; Crtd /date: USMAN/031208; Custom_Duty: 15%; Customs_HS_Code: 85332119; Distributor_name: DIGIKEY; Distributor_part_number: P3.74KLCT-ND; Footprint Path: Y:\MIS_DATABASE\Library\ALTIUM_TOOL\PCB_FOOTPRINTS\Altium_Footprint_Lib.PcbLib; Height: 0.40MM; Library Path: Y:\MIS_DATABASE\Library\ALTIUM_TOOL\SCHEMATICS_PARTS\MS_DISCRETE_Library.schlib; Mfr_name: PANASONIC-ECG; Mfr_part_number: ERJ-2RKF3741X; Mistral Part No: 110009030640-R; Package: 0402; Part_type: RESISTORS\FIXED; Project: KHAN_HSST; RoHS: RoHS; Temperature: -55°C+155°C; Tolerance: 1%; Voltage: NA; Wattage: 1/10W; Weight: 0.8mg; Datasheet: Y:\MIS_DATABASE\DATASHEETS\RESISTORS\PAN-ERJSER_NOV17.PDF
R266 R269 R296 R300 R497 R500 R520 R522 = RESISTOR: RES 47K 1/16W 1% 0402; Chkd/date: VASANTHA/060117; Crtd /date: MAZHAR/141206; Custom_Duty: 15%; Customs_HS_Code: 85332119; Distributor_name: DIGIKEY; Distributor_part_number: 311-47.0KLRCT-ND; Footprint Path: Y:\MIS_DATABASE\Library\ALTIUM_TOOL\PCB_FOOTPRINTS\Altium_Footprint_Lib.PcbLib; Height: 0.40MM; Library Path: Y:\MIS_DATABASE\Library\ALTIUM_TOOL\SCHEMATICS_PARTS\MS_DISCRETE_Library.schlib; Mfr_name: YAGEO AMERICA; Mfr_part_number: RC0402FR-0747KL; Mistral Part No: 110009030884-R; Package: 0402; Part_type: RESISTORS\FIXED; Project: ADR1B; RoHS: RoHS; Temperature: -55°C+155°C; Tolerance: 1%; Voltage: NA; Wattage: 1/16W; Weight: 0.65mg; Datasheet: Y:\MIS_DATABASE\DATASHEETS\RESISTORS\RCXXXXL-SER_MAR18.PDF
U20 U22-U24 U31 U33 U52 U56 U57 = OPA2350UA_SOIC8: IC 20MHz 1.8V LOW NOISE RRI/O CMOS OPAMP VSSOP8; Chkd/date: MANIRAJA/161018; Crtd /date: ALVY/161018; Custom_Duty: 15%; Customs_HS_Code: 85423100; Distributor_name: DIGIKEY; Distributor_part_number: 296-41349-1-ND; Footprint Path: Y:\MIS_DATABASE\Library\ALTIUM_TOOL\PCB_FOOTPRINTS\Altium_Footprint_Lib.PcbLib; Height: 1.10MM; Library Path: Y:\MIS_DATABASE\Library\ALTIUM_TOOL\SCHEMATICS_PARTS\MS_OPAMP_Library.schlib; Mfr_name: TEXAS INSTRUMENTS; Mistral Part No: 140118100019-R; Package: VSSOP8; Part_type: ICS\ANALOG\OPAMP; Project: TI_J7ES_EVM_CP; RoHS: RoHS; Temperature: -40°C+125°C; Tolerance: NA; Voltage: NA; Wattage: NA; Weight: 26.5mg; Datasheet: Y:\MIS_DATABASE\DATASHEETS\ICS\OPAMP\OPA2322XX.PDF
C98 C115 C123 C337 = CAP: CAP CERAMIC 2200pF 50V 5% X7R 0402; Chkd/date: MANIRAJA/030619; Crtd /date: ALVY/310519; Custom_Duty: 15%; Customs_HS_Code: 85322990; Distributor_name: DIGIKEY; Distributor_part_number: 1276-1532-1-ND; Footprint Path: Y:\MIS_DATABASE\Library\ALTIUM_TOOL\PCB_FOOTPRINTS\Altium_Footprint_Lib.PcbLib; Height: 0.55MM; Library Path: Y:\MIS_DATABASE\Library\ALTIUM_TOOL\SCHEMATICS_PARTS\MS_DISCRETE_Library.schlib; Mfr_name: SAMSUNG; Mfr_part_number: CL05B222JB5NNNC; Mistral Part No: 120013090018-R; Package: 0402; Part_type: CAPACITORS\CERAMIC; Project: J7ES_SOM_DUAL-LEO_PMIC; RoHS: RoHS; Temperature: -55°C+125°C; Tolerance: 5%; Voltage: 50V; Wattage: NA; Weight: NA; Datasheet: Y:\MIS_DATABASE\DATASHEETS\CAPACITORS\CL05B222JB5NNNC.PDF
C125 C335 = CAP: CAP CERAMIC 0.01uF 50V 10% X7R 0402; Chkd/date: SHREESHAIL/301105; Crtd /date: MAZHAR/040505; Custom_Duty: 15%; Customs_HS_Code: 85322990; Distributor_name: DIGIKEY; Distributor_part_number: 399-3066-1-ND; Footprint Path: Y:\MIS_DATABASE\Library\ALTIUM_TOOL\PCB_FOOTPRINTS\Altium_Footprint_Lib.PcbLib; Height: 0.55MM; Library Path: Y:\MIS_DATABASE\Library\ALTIUM_TOOL\SCHEMATICS_PARTS\MS_DISCRETE_Library.schlib; Mfr_name: KEMET; Mfr_part_number: C0402C103K5RACTU; Mistral Part No: 120009030025-R; Package: 0402; Part_type: CAPACITORS\CERAMIC; Project: G4_SVGA; RoHS: RoHS; Temperature: -55°C+125°C; Tolerance: 10%; Voltage: 50V; Wattage: NA; Weight: 0.65mg; Datasheet: Y:\MIS_DATABASE\DATASHEETS\CAPACITORS\KEMET-C-X7R.PDF
C108 C121 C129 C333 = CAP: CAP CERAMIC 22pF 50V 5% C0G(NP0) 0402; Chkd/date: MANIRAJA/060619; Crtd /date: MANIRAJA/060619; Custom_Duty: 15%; Customs_HS_Code: 85322990; Distributor_name: DIGIKEY; Distributor_part_number: 1276-1116-1-ND; Footprint Path: Y:\MIS_DATABASE\Library\ALTIUM_TOOL\PCB_FOOTPRINTS\Altium_Footprint_Lib.PcbLib; Height: 0.55MM; Library Path: Y:\MIS_DATABASE\Library\ALTIUM_TOOL\SCHEMATICS_PARTS\MS_DISCRETE_Library.schlib; Mfr_name: SAMSUNG; Mfr_part_number: CL05C220JB5NNNC; Mistral Part No: 120014100023-R; Package: 0402; Part_type: CAPACITORS\CERAMIC; Project: J7ES_SOM_DUAL-LEO_PMIC; RoHS: RoHS; Temperature: -55°C+125°C; Tolerance: 5%; Voltage: 50V; Wattage: NA; Weight: 0.65mg; Datasheet: Y:\MIS_DATABASE\DATASHEETS\CAPACITORS\CL05C220JB5NNNC.PDF
R180 R194 R200 R457 = RESISTOR: RES 3K 1/10W 5% 0402; Chkd/date: MAZHAR/150709; Crtd /date: MAZHAR/110907; Custom_Duty: 15%; Customs_HS_Code: 85332119; Distributor_name: DIGIKEY; Distributor_part_number: P3.0KJCT-ND; Footprint Path: Y:\MIS_DATABASE\Library\ALTIUM_TOOL\PCB_FOOTPRINTS\Altium_Footprint_Lib.PcbLib; Height: 0.40MM; Library Path: Y:\MIS_DATABASE\Library\ALTIUM_TOOL\SCHEMATICS_PARTS\MS_DISCRETE_Library.schlib; Mfr_name: PANASONIC-ECG; Mfr_part_number: ERJ-2GEJ302X; Mistral Part No: 110009030764-R; Package: 0402; Part_type: RESISTORS\FIXED; Project: TELEMETRY ENCODER; RoHS: RoHS; Temperature: -55°C+155°C; Tolerance: 5%; Voltage: NA; Wattage: 1/10W; Weight: 0.8mg; Datasheet: Y:\MIS_DATABASE\DATASHEETS\RESISTORS\PAN-ERJSER_NOV17.PDF
R173 R179 R184 R191 R198 R201 R203 R205 R209 R450 R452 R456 = RESISTOR: RES 1.5K 1/16W 5% 0402; Chkd/date: MANIRAJA/310718; Crtd /date: BAVISH/021210; Custom_Duty: 15%; Customs_HS_Code: 85332119; Distributor_name: DIGIKEY; Distributor_part_number: 311-1.5KJRCT-ND; Footprint Path: Y:\MIS_DATABASE\Library\ALTIUM_TOOL\PCB_FOOTPRINTS\Altium_Footprint_Lib.PcbLib; Height: 0.40MM; Library Path: Y:\MIS_DATABASE\Library\ALTIUM_TOOL\SCHEMATICS_PARTS\MS_DISCRETE_Library.schlib; Mfr_name: YAGEO AMERICA; Mfr_part_number: RC0402JR-071K5L; Mistral Part No: 110010120012-R; Package: 0402; Part_type: RESISTORS\FIXED; Project: TE4; RoHS: RoHS; Temperature: -55°C+155°C; Tolerance: 5%; Voltage: NA; Wattage: 1/16W; Weight: 0.65mg; Datasheet: Y:\MIS_DATABASE\DATASHEETS\RESISTORS\RCXXXXL-SER_MAR18.PDF
R172 R186 R189 R202 R204 R207 R451 R455 = RESISTOR: RES 47E 1/16W 5% 0402; Chkd/date: MANIRAJA/250319; Crtd /date: MANIRAJA/250319; Custom_Duty: 15%; Customs_HS_Code: 85332119; Distributor_name: DIGIKEY; Distributor_part_number: 311-47JRCT-ND; Footprint Path: Y:\MIS_DATABASE\Library\ALTIUM_TOOL\PCB_FOOTPRINTS\Altium_Footprint_Lib.PcbLib; Height: 0.40MM; Library Path: Y:\MIS_DATABASE\Library\ALTIUM_TOOL\SCHEMATICS_PARTS\MS_DISCRETE_Library.schlib; Mfr_name: YAGEO AMERICA; Mfr_part_number: RC0402JR-0747RL; Mistral Part No: 110019040221-R; Package: 0402; Part_type: RESISTORS\FIXED; Project: POWERBOX; RoHS: RoHS; Temperature: -55°C+155°C; Tolerance: 5%; Voltage: NA; Wattage: 1/16W; Weight: 0.65mg; Datasheet: Y:\MIS_DATABASE\DATASHEETS\RESISTORS\RCXXXXL-SER_MAR18.PDF
C106 C117 = CAP: CAP CERAMIC 3.3pF 50V 0.25pF C0G(NP0) 0402; Chkd/date: SHREESHAIL/281105; Crtd /date: MAZHAR/211005; Custom_Duty: 15%; Customs_HS_Code: 85322990; Distributor_name: DIGIKEY; Distributor_part_number: 478-1064-1-ND; Footprint Path: Y:\MIS_DATABASE\Library\ALTIUM_TOOL\PCB_FOOTPRINTS\Altium_Footprint_Lib.PcbLib; Height: 0.56MM; Library Path: Y:\MIS_DATABASE\Library\ALTIUM_TOOL\SCHEMATICS_PARTS\MS_DISCRETE_Library.schlib; Mfr_name: AVX CORPORATION; Mfr_part_number: 04025A3R3CAT2A; Mistral Part No: 120009030354-R; Package: 0402; Part_type: CAPACITORS\CERAMIC; Project: EPDA_CORE; RoHS: RoHS; Temperature: -55°C+125°C; Tolerance: 0.25pF%; Voltage: 50V; Wattage: NA; Weight: 0.65mg; Datasheet: Y:\MIS_DATABASE\DATASHEETS\CAPACITORS\AVX_MLC.PDF
C111 C114 = CAP: CAP CERAMIC 2.2uF 50V 20% X7R 0805; Chkd/date: MANIRAJA/241018; Crtd /date: ALVY/241018; Custom_Duty: 15%; Customs_HS_Code: 85322990; Distributor_name: DIGIKEY; Distributor_part_number: 445-172488-1-ND; Footprint Path: Y:\MIS_DATABASE\Library\ALTIUM_TOOL\PCB_FOOTPRINTS\Altium_Footprint_Lib.PcbLib; Height: 1.50MM; Library Path: Y:\MIS_DATABASE\Library\ALTIUM_TOOL\SCHEMATICS_PARTS\MS_DISCRETE_Library.schlib; Mfr_name: TDK CORPORATION; Mfr_part_number: C2012X7R1H225M125AE; Mistral Part No: 120018100054-R; Package: 0805; Part_type: CAPACITORS\CERAMIC; Project: TI_J7ES_EVM_CP; RoHS: RoHS; Temperature: -55°C+125°C; Tolerance: 20%; Voltage: 50V; Wattage: NA; Weight: 5.5mg; Datasheet: Y:\MIS_DATABASE\DATASHEETS\CAPACITORS\TDK-CAP-E-SER.PDF
R175 R199 = RESISTOR: RES 49.9E 1/10W 1% 0402; Chkd/date: VASANTHA/201216; Crtd /date: MAZHAR/201005; Custom_Duty: 15%; Customs_HS_Code: 85332119; Distributor_name: DIGIKEY; Distributor_part_number: P49.9LCT-ND; Footprint Path: Y:\MIS_DATABASE\Library\ALTIUM_TOOL\PCB_FOOTPRINTS\Altium_Footprint_Lib.PcbLib; Height: 0.40MM; Library Path: Y:\MIS_DATABASE\Library\ALTIUM_TOOL\SCHEMATICS_PARTS\MS_DISCRETE_Library.schlib; Mfr_name: PANASONIC-ECG; Mfr_part_number: ERJ-2RKF49R9X; Mistral Part No: 110009030897-R; Package: 0402; Part_type: RESISTORS\FIXED; Project: RED EYE; RoHS: RoHS; Temperature: -55°C+155°C; Tolerance: 1%; Voltage: NA; Wattage: 1/10W; Weight: 0.8mg; Datasheet: Y:\MIS_DATABASE\DATASHEETS\RESISTORS\PAN-ERJSER_NOV17.PDF
R176 R195 = RESISTOR: RES 100K 1/16W 5% 0402; Assembly_Instruction: DNI; Chkd/date: VASANTHA/130516; Crtd /date: VASANTHA/130516; Custom_Duty: 15%; Customs_HS_Code: 85332119; Distributor_name: DIGIKEY; Distributor_part_number: A121521CT-ND; Footprint Path: Y:\MIS_DATABASE\Library\ALTIUM_TOOL\PCB_FOOTPRINTS\Altium_Footprint_Lib.PcbLib; Height: 0.40MM; Library Path: Y:\MIS_DATABASE\Library\ALTIUM_TOOL\SCHEMATICS_PARTS\MS_DISCRETE_Library.schlib; Mfr_name: TE CONNECTIVITY; Mfr_part_number: CRG0402J100K/10; Mistral Part No: 110019040062-R; Package: 0402; Part_type: RESISTORS\FIXED; Project: TMDXCSK368; RoHS: RoHS; Temperature: -55°C+125°C; Tolerance: 5%; Voltage: NA; Wattage: 1/16W; Weight: 0.65mg; Datasheet: Y:\MIS_DATABASE\DATASHEETS\RESISTORS\CRG-SERIES.PDF
R177 R185 R190 R196 = RESISTOR: RES 0E 1/10W JUMPER 0402; Chkd/date: VASANTHA/061216; Crtd /date: NAVEED/201014; Custom_Duty: 15%; Customs_HS_Code: 85332119; Distributor_name: DIGIKEY; Distributor_part_number: P0.0JCT-ND; Footprint Path: Y:\MIS_DATABASE\Library\ALTIUM_TOOL\PCB_FOOTPRINTS\Altium_Footprint_Lib.PcbLib; Height: 0.40MM; IBISSP_MODLES: VALUE REPEATING 2 TIME; Library Path: Y:\MIS_DATABASE\Library\ALTIUM_TOOL\SCHEMATICS_PARTS\MS_DISCRETE_Library.schlib; Mfr_name: PANASONIC-ECG; Mfr_part_number: ERJ-2GE0R00X; Mistral Part No: 110018030052-R; Package: 0402; Part_type: RESISTORS\FIXED; Project: AEGIS POM; RoHS: RoHS; Temperature: -55°C+155°C; Tolerance: NA; Voltage: NA; Wattage: 1/10W; Weight: 0.8mg; Datasheet: Y:\MIS_DATABASE\DATASHEETS\RESISTORS\PAN-ERJSER_NOV17.PDF
R178 R197 = RESISTOR: RES 0E 1/10W JUMPER 0402; Assembly_Instruction: DNI; Chkd/date: VASANTHA/061216; Crtd /date: NAVEED/201014; Custom_Duty: 15%; Customs_HS_Code: 85332119; Distributor_name: DIGIKEY; Distributor_part_number: P0.0JCT-ND; Footprint Path: Y:\MIS_DATABASE\Library\ALTIUM_TOOL\PCB_FOOTPRINTS\Altium_Footprint_Lib.PcbLib; Height: 0.40MM; IBISSP_MODLES: VALUE REPEATING 2 TIME; Library Path: Y:\MIS_DATABASE\Library\ALTIUM_TOOL\SCHEMATICS_PARTS\MS_DISCRETE_Library.schlib; Mfr_name: PANASONIC-ECG; Mfr_part_number: ERJ-2GE0R00X; Mistral Part No: 110018030052-R; Package: 0402; Part_type: RESISTORS\FIXED; Project: AEGIS POM; RoHS: RoHS; Temperature: -55°C+155°C; Tolerance: NA; Voltage: NA; Wattage: 1/10W; Weight: 0.8mg; Datasheet: Y:\MIS_DATABASE\DATASHEETS\RESISTORS\PAN-ERJSER_NOV17.PDF
R181 R193 = RESISTOR: RES 150K 1/10W 1% 0402; Chkd/date: SHREESHAIL/200906; Crtd /date: MAZHAR/190906; Custom_Duty: 15%; Customs_HS_Code: 85332119; Distributor_name: DIGIKEY; Distributor_part_number: P150KLCT-ND; Footprint Path: Y:\MIS_DATABASE\Library\ALTIUM_TOOL\PCB_FOOTPRINTS\Altium_Footprint_Lib.PcbLib; Height: 0.40MM; Library Path: Y:\MIS_DATABASE\Library\ALTIUM_TOOL\SCHEMATICS_PARTS\MS_DISCRETE_Library.schlib; Mfr_name: PANASONIC-ECG; Mfr_part_number: ERJ-2RKF1503X; Mistral Part No: 110009030336-R; Package: 0402; Part_type: RESISTORS\FIXED; Project: SM2_AFE; RoHS: RoHS; Temperature: -55°C+155°C; Tolerance: 1%; Voltage: NA; Wattage: 1/10W; Weight: 0.8mg; Datasheet: Y:\MIS_DATABASE\DATASHEETS\RESISTORS\PAN-ERJSER_NOV17.PDF
R182 R192 = RESISTOR: RES 5.9K 1/10W 1% 0402; Chkd/date: MAZHAR/251110; Crtd /date: BAVISH/251110; Custom_Duty: 15%; Customs_HS_Code: 85332119; Distributor_name: DIGIKEY; Distributor_part_number: P5.90KLCT-ND; Footprint Path: Y:\MIS_DATABASE\Library\ALTIUM_TOOL\PCB_FOOTPRINTS\Altium_Footprint_Lib.PcbLib; Height: 0.40MM; Library Path: Y:\MIS_DATABASE\Library\ALTIUM_TOOL\SCHEMATICS_PARTS\MS_DISCRETE_Library.schlib; Mfr_name: PANASONIC-ECG; Mfr_part_number: ERJ-2RKF5901X; Mistral Part No: 110010110029-R; Package: 0402; Part_type: RESISTORS\FIXED; Project: CENTAURUS; RoHS: RoHS; Temperature: -55°C+155°C; Tolerance: 1%; Voltage: NA; Wattage: 1/10W; Weight: 0.8mg; Datasheet: Y:\MIS_DATABASE\DATASHEETS\RESISTORS\PAN-ERJSER_NOV17.PDF

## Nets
DGND: C60.2 C61.2 C62.2 C63.2 C99.2 C103.2 C107.2 C113.2 C116.2 C124.2 C175.2 C201.2 C203.2 C324.2 C328.2 C334.2 C336.2 C365.2 C379.2 C767.2 C768.2 J13.1B J15.1A J18.1A J18.1B J19.1A J19.1B R176.1 R195.1 R254.2 R266.2 R269.2 R273.2 R289.2 R296.2 R300.2 R301.2 R487.2 R497.2 R500.2 R501.2 R513.2 R520.2 R522.2 R523.2 U20.4(V-) U22.4(V-) U23.4(V-) U24.4(V-) U31.4(V-) U33.4(V-) U52.4(V-) U56.4(V-) U57.4(V-) ; also on sheet 5 6 7 8 12 13 14 15 16 17 18 19 20 21 22 23 25
VCC_5V0: C61.1 C63.1 FL7.2 ; also on sheet 5 6 14 15 17 22 23
VCCP_IN: C99.1 C107.1 C116.1 C328.1 C334.1 U20.8(V+) U22.8(V+) U23.8(V+) U24.8(V+) U52.8(V+) ; also on sheet 6 7 8 12 22 23
VCCP_OUT: C60.1 C62.1 C175.1 C201.1 C203.1 C365.1 C379.1 FL7.1 R250.1 R268.1 R286.1 R299.1 R482.1 R499.1 R510.1 R521.1 U31.8(V+) U33.8(V+) U56.8(V+) U57.8(V+) ; also on sheet 13
AOUT1_a: C376.1 R511.2 R512.1 R517.2 R519.2
AOUT1_b: C376.2 R515.1 R516.2 R517.1 R518.2
AOUT1_c: C374.1 R511.1 U57.2(-INA)
AOUT1_d: C377.1 R518.1 U57.3(+INA)
AOUT1_e: C377.2 R510.2 R513.1 R515.2
AOUT1_N: C378.2 ; also on sheet 23
AOUT1_o: C374.2 R512.2 R514.1 U57.1(OUTA)
AOUT1_P: C375.2 ; also on sheet 23
AOUT1N: C378.1 R519.1
AOUT1P: C375.1 R516.1
AOUT2_a: C383.1 R527.1 R529.2 R530.1 R531.2
AOUT2_b: C383.2 R524.1 R525.2 R527.2 R528.2
AOUT2_c: C381.1 R529.1 U57.6(-INB)
AOUT2_d: C384.1 R528.1 U57.5(+INB)
AOUT2_e: C384.2 R521.2 R523.1 R524.2
AOUT2_N: C385.2 ; also on sheet 23
AOUT2_o: C381.2 R526.1 R530.2 U57.7(OUTB)
AOUT2_P: C382.2 ; also on sheet 23
AOUT2N: C385.1 R531.1
AOUT2P: C382.1 R525.1
AOUT3_a: C208.1 R306.1 R307.1 R308.2 R309.2
AOUT3_b: C208.2 R302.1 R303.2 R305.2 R306.2
AOUT3_c: C205.1 R308.1 U33.2(-INA)
AOUT3_d: C207.1 R305.1 U33.3(+INA)
AOUT3_e: C207.2 R299.2 R301.1 R302.2
AOUT3_N: C209.2 ; also on sheet 23
AOUT3_o: C205.2 R304.1 R307.2 U33.1(OUTA)
AOUT3_P: C206.2 ; also on sheet 23
AOUT3N: C209.1 R309.1
AOUT3P: C206.1 R303.1
AOUT4_a: C200.1 R287.1 R288.2 R294.1 R295.2
AOUT4_b: C200.2 R291.1 R292.2 R293.2 R294.2
AOUT4_c: C197.1 R288.1 U33.6(-INB)
AOUT4_d: C199.1 R293.1 U33.5(+INB)
AOUT4_e: C199.2 R286.2 R289.1 R291.2
AOUT4_N: C202.2 ; also on sheet 23
AOUT4_o: C197.2 R287.2 R290.1 U33.7(OUTB)
AOUT4_P: C198.2 ; also on sheet 23
AOUT4N: C202.1 R295.1
AOUT4P: C198.1 R292.1
AOUT5_a: C362.1 R483.2 R484.1 R494.1 R496.2
AOUT5_b: C362.2 R492.1 R493.2 R494.2 R495.2
AOUT5_c: C360.1 R483.1 U56.2(-INA)
AOUT5_d: C363.1 R495.1 U56.3(+INA)
AOUT5_e: C363.2 R482.2 R487.1 R492.2
AOUT5_N: C364.2 ; also on sheet 23
AOUT5_o: C360.2 R484.2 R488.1 U56.1(OUTA)
AOUT5_P: C361.2 ; also on sheet 23
AOUT5N: C364.1 R496.1
AOUT5P: C361.1 R493.1
AOUT6_a: C370.1 R505.1 R507.2 R508.1 R509.2
AOUT6_b: C370.2 R502.1 R503.2 R505.2 R506.2
AOUT6_c: C367.1 R507.1 U56.6(-INB)
AOUT6_d: C371.1 R506.1 U56.5(+INB)
AOUT6_e: C371.2 R499.2 R501.1 R502.2
AOUT6_N: C372.2 ; also on sheet 23
AOUT6_o: C367.2 R504.1 R508.2 U56.7(OUTB)
AOUT6_P: C368.2 ; also on sheet 23
AOUT6N: C372.1 R509.1
AOUT6P: C368.1 R503.1
AOUT7_a: C187.1 R282.1 R283.1 R284.2 R285.2
AOUT7_b: C187.2 R275.1 R279.2 R281.2 R282.2
AOUT7_c: C184.1 R284.1 U31.2(-INA)
AOUT7_d: C186.1 R281.1 U31.3(+INA)
AOUT7_e: C186.2 R268.2 R273.1 R275.2
AOUT7_N: C189.2 ; also on sheet 23
AOUT7_o: C184.2 R280.1 R283.2 U31.1(OUTA)
AOUT7_P: C185.2 ; also on sheet 23
AOUT7N: C189.1 R285.1
AOUT7P: C185.1 R279.1
AOUT8_a: C173.1 R252.1 R253.2 R262.1 R265.2
AOUT8_b: C173.2 R258.1 R259.2 R261.2 R262.2
AOUT8_c: C169.1 R253.1 U31.6(-INB)
AOUT8_d: C172.1 R261.1 U31.5(+INB)
AOUT8_e: C172.2 R250.2 R254.1 R258.2
AOUT8_N: C177.2 ; also on sheet 23
AOUT8_o: C169.2 R252.2 R255.1 U31.7(OUTB)
AOUT8_P: C170.2 ; also on sheet 23
AOUT8N: C177.1 R265.1
AOUT8P: C170.1 R259.1
BIN1_N: C104.2 R172.2 R173.2 R179.2 ; also on sheet 22
BIN1_P: C104.1 R184.2 R186.2 ; also on sheet 22
BIN2_N: C120.2 R189.2 R191.2 R198.2 ; also on sheet 22
BIN2_P: C120.1 R203.2 R204.2 ; also on sheet 22
BIN5_N: C335.1 R452.2 R455.2 R456.2 ; also on sheet 22
BIN5_P: C335.2 R450.2 R451.2 ; also on sheet 22
BIN6_N: C125.1 R201.2 R202.2 R205.2 ; also on sheet 22
BIN6_P: C125.2 R207.2 R209.2 ; also on sheet 22
CODECA_VOUT1: C373.2 J19.5B R520.1
CODECA_VOUT2: C380.2 J19.2B R522.1
CODECA_VOUT3: C204.2 J19.5A R300.1
CODECA_VOUT4: C196.2 J19.2A R296.1
CODECA_VOUT5: C359.2 J18.5B R497.1
CODECA_VOUT6: C366.2 J18.2B R500.1
CODECA_VOUT7: C183.2 J18.5A R269.1
CODECA_VOUT8: C168.2 J18.2A R266.1
CODECB_LIN_L: C338.2 J15.5A
CODECB_LIN_L_ac: C338.1 R457.1
CODECB_LIN_R: C122.2 J15.2A
CODECB_LIN_R_ac: C122.1 R200.1
CODECB_MIC1_L: J13.5B R178.1 R185.1
CODECB_MIC1_R: J13.2B R190.1 R197.1
LINB_L_a: C337.2 R455.1 U52.1(OUTA)
LINB_L_b: C337.1 R456.1 R457.2 U52.2(-INA)
LINB_L_c: C333.1 R450.1 R452.1 U52.6(-INB)
LINB_L_d: C333.2 R451.1 U52.7(OUTB)
LINB_R_a: C123.2 R202.1 U24.1(OUTA)
LINB_R_b: C123.1 R200.2 R201.1 U24.2(-INA)
LINB_R_c: C129.1 R205.1 R209.1 U24.6(-INB)
LINB_R_d: C129.2 R207.1 U24.7(OUTB)
MIC1BL_a: C98.2 R172.1 U20.7(OUTB)
MIC1BL_ac: C105.1 R180.1
MIC1BL_b: C98.1 R173.1 R180.2 U20.6(-INB)
MIC1BL_BIAS: C111.2 R182.2 R185.2
MIC1BL_BIAS_ac: C106.1 C111.1 R181.1 U22.6(-INB)
MIC1BL_c: C108.1 R179.1 R184.1 U20.2(-INA)
MIC1BL_d: C108.2 R186.1 U20.1(OUTA)
MIC1BL_PRE: C106.2 R175.1 R181.2 U22.7(OUTB)
MIC1BR_a: C115.2 R189.1 U23.7(OUTB)
MIC1BR_ac: C118.1 R194.1
MIC1BR_b: C115.1 R191.1 R194.2 U23.6(-INB)
MIC1BR_BIAS: C114.2 R190.2 R192.2
MIC1BR_BIAS_ac: C114.1 C117.1 R193.1 U22.2(-INA)
MIC1BR_c: C121.1 R198.1 R203.1 U23.2(-INA)
MIC1BR_d: C121.2 R204.1 U23.1(OUTA)
MIC1BR_PRE: C117.2 R193.2 R199.1 U22.1(OUTA)
VCOMAD2: C103.1 C113.1 C124.1 C324.1 C336.1 C767.1 C768.1 R182.1 R192.1 U20.3(+INA) U20.5(+INB) U22.3(+INA) U22.5(+INB) U23.3(+INA) U23.5(+INB) U24.3(+INA) U24.5(+INB) U52.3(+INA) U52.5(+INB) ; also on sheet 12 22
N23670479: C204.1 R304.2
N23670482: C196.1 R290.2
N24488350: C373.1 R514.2
N24488546: C380.1 R526.2
N24492127: C183.1 R280.2
N24492135: C359.1 R488.2
N24492520: C168.1 R255.2
N24492543: C366.1 R504.2
N24497380: C118.2 R196.2 R197.2
N24497698: R195.2 R196.1 R199.2
N24498184: R175.2 R176.2 R177.1
N24498190: C105.2 R177.2 R178.2

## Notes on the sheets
sheet 9
- CODEC-A STEREO LINE OUT
- Note: Full scale is 8Vpp differentially
- Note: Full scale is 8Vpp differentially
- Gain = 0.747; f–3 dB = 53 kHz
- Gain = 0.747; f–3 dB = 53 kHz
- J19-TOP JACK
  LOUT L CODEC-A VOUT3
  LOUT R CODEC-A VOUT4
- J19-BOTTOM JACK
  LOUT L CODEC-A VOUT1
  LOUT R CODEC-A VOUT2
- Silkscreen: "CODEC-A LINE-OUT 3/4, 1/2"
- Note: Full scale is 8Vpp differentially
- Note: Full scale is 8Vpp differentially
- Gain = 0.747; f–3 dB = 53 kHz
- Gain = 0.747; f–3 dB = 53 kHz
- J18-TOP JACK
  LOUT L CODEC-A VOUT7
  LOUT R CODEC-A VOUT8
- J18-BOTTOM JACK
  LOUT L CODEC-A VOUT5
  LOUT R CODEC-A VOUT6
- Silkscreen: "CODEC-A LINE-OUT 7/8, 5/6"
- Audio Op-Amp Supply Filter
sheet 10
- CODEC-B STEREO LINE IN
- J15-TOP JACK
  LIN L CODEC-B VIN5
  LIN R CODEC-B VIN6
- To AUDIO
  CODEC-B VIN6
- Note: Full scale is 2Vrms  differentially
- Note:  Full scale input is 2Vrms.
- Note: Gain = 1, f-3dB = 48kHz
- Silkscreen:
  "CODEC-B LIN"
- To AUDIO
  CODEC-B VIN5
- Note: Full scale is 2Vrms  differentially
- Note: Gain = 1, f-3dB = 48kHz
- Single-Ended to Differential Buffer w/ Anti-Aliasing LPF
sheet 11
- CODEC-B STEREO MICROPHONE 1
- Single-Ended to Differential Buffer w/ Anti-Aliasing LPF
- "R1"
- BIAS
- PRE AMPLIFIER
- See Config
  Table
- To AUDIO
  CODEC-B VIN2
- Note: Full scale is 2Vrms  differentially
- "R3"
- Note: Gain = 1, f-3dB = 48kHz
- J13-BOTTOM JACK
  MICIN L CODEC-B VIN1
  MICIN R CODEC-B VIN2
- See Config
  Table
- "R2"
- "R5"
- Silkscreen:
  "CODEC-A MIC 1 & 2"
- BIAS
- PRE AMPLIFIER
- To AUDIO
  CODEC-B VIN1
- Note: Full scale is 2Vrms  differentially
- "R6"
- Note: Gain = 1, f-3dB = 48kHz
- See Config
  Table
- "R4"
- Config Table
- Install
- Remove
- PASSIVE-MIC
- R2,R3,R5,R6
- R1,R4
- (default)
- BIAS + PREAMP
- ACTIVE-MIC
- BIAS ONLY
- R1,R2,R4,R5
- R3,R6
- LINE-INPUT
- NO BIAS/PREAMP
- R1,R4
- R2,R3,R5,R6
